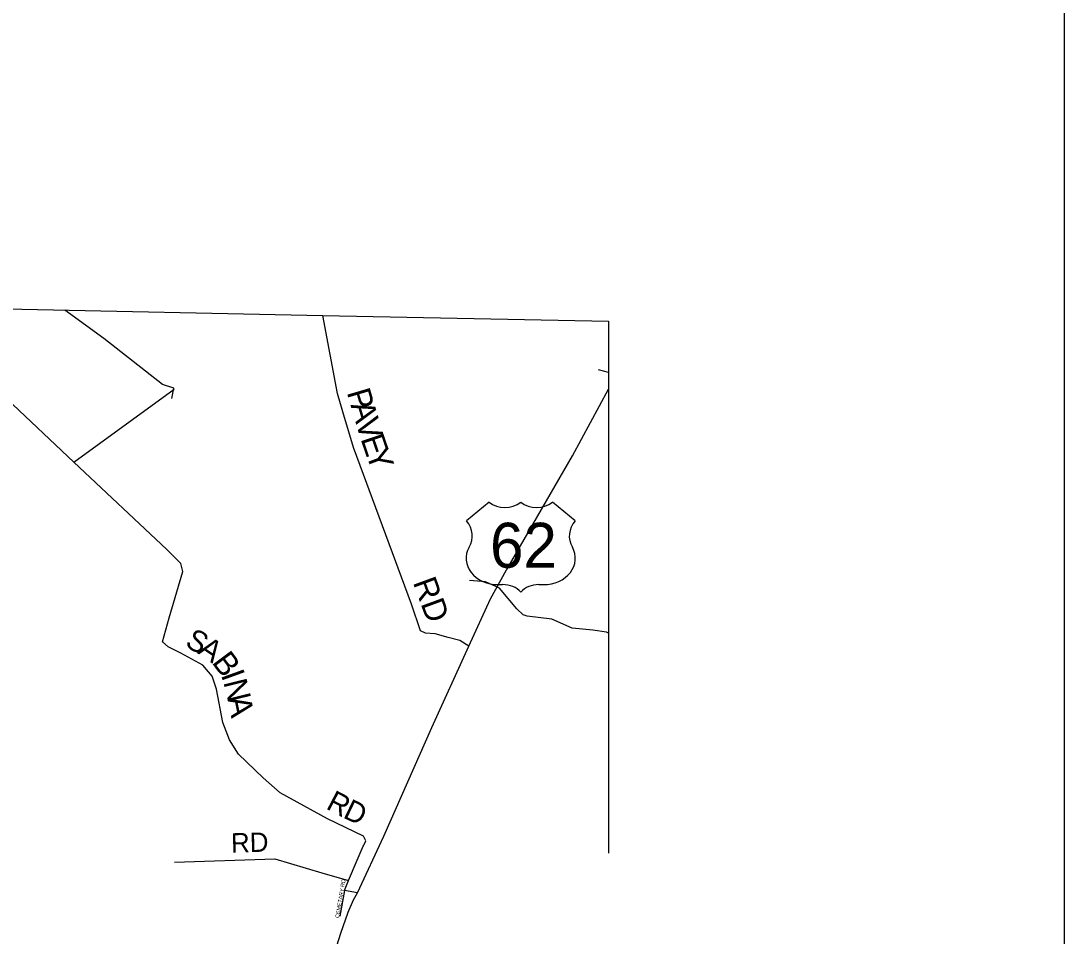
# Model space of a CAD drawing. Extents: x 0 to 784, y 0 to 440.
# Drawn here: x 367.9 to 465.8, y 100.9 to 186.8 of the extents above; entities that cross this region are included whole.
import ezdxf

# ---------------------------------------------------------------- set-up
doc = ezdxf.new("R2010")
doc.units = 0
doc.layers.add('Default', color=7, linetype='Continuous')

msp = doc.modelspace()

# ---------------------------------------------------------------- linework, layer by layer
at = {"layer": 'Default'}
for p, q in [((411.808, 141.597), (409.686, 139.839)), ((419.871, 139.839), (417.749, 141.597)), ((412.656, 133.862), (413.081, 133.862)), ((416.476, 133.862), (416.9, 133.862))]:
    msp.add_line(p, q, dxfattribs=at)
msp.add_lwpolyline([(31.327, 429.991), (465.774, 429.991), (465.774, 10.05), (31.327, 10.05)], close=True, dxfattribs=at)
for points in [[(328.56, 159.014), (366.446, 159.73), (396.217, 159.125), (423.029, 158.579)], [(400.1, 109.529), (400.239, 109.805), (400.007, 110.256), (396.653, 111.867), (392.187, 114.324), (390.609, 115.731), (388.288, 117.956), (387.431, 119.299), (386.825, 120.907), (386.231, 124.048), (385.813, 125.267), (384.939, 126.317), (382.889, 127.435), (381.688, 128.025), (381.147, 128.49), (381.796, 130.737), (383.063, 135.096), (382.878, 135.839), (381.564, 137.147), (372.842, 145.352), (366.537, 151.284), (366.446, 159.73)], [(382.039, 151.337), (382.218, 152.29), (381.168, 152.654), (375.64, 156.968), (372.003, 159.624)], [(409.911, 128.097), (409.053, 128.609), (407.967, 128.907), (406.749, 129.254), (405.838, 129.32), (405.369, 129.529), (404.52, 132.014), (399.087, 146.735), (398.082, 150.085), (397.595, 151.802), (396.217, 159.125)], [(423.029, 158.579), (423.029, 108.656)], [(423.029, 153.765), (422.089, 154.004)], [(372.842, 145.352), (382.249, 152.212)], [(413.46, 135.264), (419.644, 145.936), (423.029, 152.2)], [(397.261, 98.958), (397.314, 99.147), (397.513, 99.963), (397.891, 101.156), (398.579, 103.136), (399.073, 104.286), (399.447, 104.946), (401.918, 110.264), (406.439, 120.466), (409.911, 128.097), (411.93, 132.535), (413.444, 135.237), (413.46, 135.264)], [(423.029, 129.32), (422.818, 129.392), (421.529, 129.579), (419.607, 129.774), (417.683, 130.613), (415.381, 130.897), (415.002, 131.036), (414.41, 131.579), (412.786, 133.533), (411.475, 134.133), (409.978, 134.237)], [(399.447, 104.946), (398.232, 105.163), (398.622, 106.096), (399.417, 107.997), (400.001, 109.332), (400.045, 109.421), (400.1, 109.529)], [(382.274, 107.82), (391.7, 108.124), (396.115, 106.799), (398.622, 106.096)], [(398.232, 105.163), (397.811, 102.757)]]:
    msp.add_lwpolyline(points, dxfattribs=at)
for centre, major_axis, start_param, end_param in [((413.293, 142.853), (2.122, 0), 3.936991, 5.487786), ((416.264, 142.853), (2.122, 0), 3.936991, 5.487786), ((407.252, 138.428), (2.971, 0), 5.838949, 6.894067), ((422.305, 138.428), (-2.971, 0), 5.672304, 6.727422), ((412.623, 136.323), (2.971, 0), 2.702327, 4.723529), ((416.934, 136.323), (2.971, 0), 4.701249, 6.722451), ((413.081, 132.104), (-2.122, 0), 3.785094, 4.712389), ((416.476, 132.104), (-2.122, 0), 4.712389, 5.639684)]:
    msp.add_ellipse(centre, major_axis=major_axis, ratio=0.82844, start_param=start_param, end_param=end_param, dxfattribs=at)

# ---------------------------------------------------------------- texts
for s, height, rotation, p in [('P', 2.194, 286.37485, (398.44, 151.919)), ('A', 2.194, 286.37042, (398.79, 150.727)), ('V', 2.194, 286.66538, (399.249, 149.164)), ('E', 2.193, 288.64847, (399.732, 147.554)), ('Y', 2.192, 290.55691, (400.193, 146.19)), ('RD', 2.1922, 290.12534, (404.635, 134.081)), ('S', 2, 330.94578, (383.179, 128.114)), ('A', 2.045, 325.69771, (384.363, 127.459)), ('B', 2.16, 306.7166, (385.729, 126.56)), ('I', 2.192, 289.92407, (386.614, 125.404)), ('N', 2.195, 283.75978, (386.861, 124.731)), ('A', 2.195, 281.415, (387.241, 123.18)), ('R', 1.986, 332.46846, (396.414, 112.865)), ('D', 1.969, 334.35069, (398.013, 112.033)), ('RD', 1.8191, 1.6354, (387.613, 108.707)), ('CEMETARY RD', 0.36583, 80.21606, (397.718, 102.556))]:
    msp.add_text(s, height=height, rotation=rotation, dxfattribs=at).set_placement(p)
msp.add_text('62', height=4.219, dxfattribs=at).set_placement((411.896, 135.444))

doc.saveas('drawing.dxf')
